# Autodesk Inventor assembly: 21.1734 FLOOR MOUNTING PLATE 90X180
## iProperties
Created: 2007-04
Part Number: 21.1734 FLOOR MOUNTING PLATE 90X180
Document SubType Name: Assembly
Designer: Andy Moles
Author: Andy Moles
Title: 20.1016 32X180  L = 7.09"
